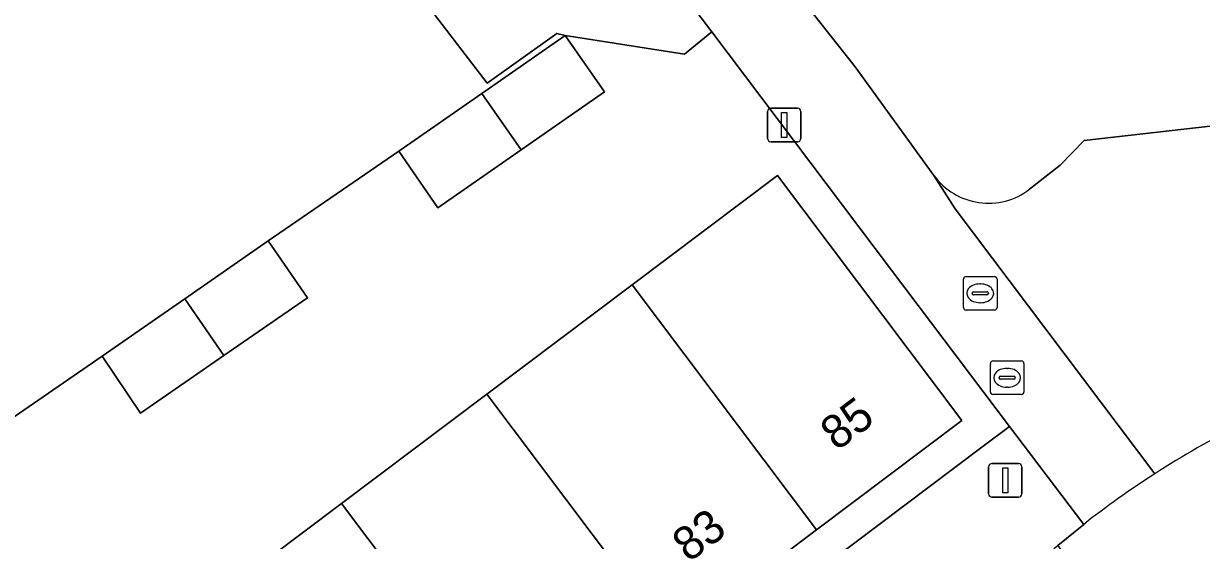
# Model space of a CAD drawing. Extents: x 160377 to 161131, y 383938 to 384853.
# Drawn here: x 160494.57 to 160529.76, y 384729.14 to 384744.58 of the extents above; entities that cross this region are included whole.
import ezdxf

# ---------------------------------------------------------------- set-up
doc = ezdxf.new("R2010")
doc.units = 0
for name, color, linetype in [('IMGEO_Brandkraan', 7, 'Continuous'), ('IMGEO_Erf', 7, 'Continuous'), ('IMGEO_Lichtmast', 7, 'Continuous'), ('IMGEO_Pand', 7, 'Continuous'), ('IMGEO_Pand_nummerreeks', 7, 'Continuous'), ('IMGEO_Rijbaan_lokaal_open', 7, 'Continuous'), ('IMGEO_Rioolput', 7, 'Continuous'), ('IMGEO_Voetpad_open', 7, 'Continuous')]:
    doc.layers.add(name, color=color, linetype=linetype)

msp = doc.modelspace()

# ---------------------------------------------------------------- linework, layer by layer
at = {"layer": 'IMGEO_Brandkraan'}
for p, q in [((160523.452, 384733.576), (160523.452, 384734.428)), ((160523.527, 384734.502), (160524.379, 384734.502)), ((160524.453, 384734.428), (160524.453, 384733.576)), ((160523.94, 384734.282), (160523.965, 384734.282)), ((160523.711, 384733.996), (160523.711, 384734.008)), ((160524.149, 384733.959), (160523.751, 384733.959)), ((160523.754, 384734.045), (160524.152, 384734.045)), ((160523.963, 384733.722), (160523.938, 384733.722)), ((160524.195, 384734.008), (160524.195, 384733.996)), ((160524.379, 384733.502), (160523.527, 384733.502))]:
    msp.add_line(p, q, dxfattribs=at)
for points in [[(160523.452, 384733.576), (160523.452, 384734.428)], [(160523.527, 384734.502), (160524.379, 384734.502)], [(160524.453, 384734.428), (160524.453, 384733.576)], [(160524.379, 384733.502), (160523.527, 384733.502)]]:
    msp.add_lwpolyline(points, dxfattribs=at)
for centre, radius, start, end in [((160523.529, 384734.426), 0.0765, 91.552, 178.448), ((160523.529, 384734.426), 0.0765, 91.552, 178.448), ((160524.377, 384734.426), 0.0765, 1.552, 88.448), ((160524.377, 384734.426), 0.0765, 1.552, 88.448), ((160523.751, 384734.005), 0.0403, 85.8775, 175.7526), ((160523.748, 384733.995), 0.0366, 178.938, 274.7102), ((160524.152, 384734.002), 0.043, 264.8664, 352.4533), ((160524.156, 384734.007), 0.0386, 1.7309, 96.639), ((160523.529, 384733.578), 0.0765, 181.552, 268.448), ((160523.529, 384733.578), 0.0765, 181.552, 268.448), ((160524.377, 384733.578), 0.0765, 271.552, 358.448), ((160524.377, 384733.578), 0.0765, 271.552, 358.448)]:
    msp.add_arc(centre, radius, start, end, dxfattribs=at)
for centre, major_axis, ratio, start_param, end_param in [((160523.939, 384734.002), (-0.387, 0.002), 0.722429, 4.712389, 7.853982), ((160523.964, 384734.002), (-0.39, 0.002), 0.717154, 1.570796, 4.712389)]:
    msp.add_ellipse(centre, major_axis=major_axis, ratio=ratio, start_param=start_param, end_param=end_param, dxfattribs=at)
at = {"layer": 'IMGEO_Erf'}
for points in [[(160524.622, 384739.63), (160525.541, 384740.344), (160526.258, 384741.081), (160536.933, 384742.304), (160543.963, 384743.13), (160555.551, 384744.527), (160559.981, 384745.061), (160564.978, 384745.652), (160564.727, 384747.719), (160559.736, 384747.162), (160557.652, 384764.913)], [(160512.869, 384751.723), (160515.948, 384747.677), (160519.414, 384743.287), (160521.768, 384740.04)], [(160501.88, 384738.087), (160505.784, 384740.768), (160508.262, 384742.49), (160510.755, 384744.223), (160510.5, 384744.276), (160508.419, 384742.793), (160504.852, 384747.466)], [(160487, 384704.676), (160523.198, 384731.929), (160524.022, 384732.549), (160520.501, 384737.216), (160515.137, 384744.326), (160514.313, 384743.664), (160510.755, 384744.223), (160511.925, 384742.54), (160509.436, 384740.806), (160506.946, 384739.072), (160505.784, 384740.768), (160501.88, 384738.087), (160503.052, 384736.392), (160500.558, 384734.669), (160498.065, 384732.947), (160496.919, 384734.648), (160492.969, 384731.932)], [(160491.047, 384720.451), (160495.388, 384723.716), (160499.729, 384726.981), (160504.07, 384730.246), (160508.411, 384733.512), (160512.752, 384736.777), (160517.093, 384740.042), (160522.597, 384732.728), (160518.257, 384729.462), (160513.917, 384726.196), (160509.576, 384722.929), (160505.236, 384719.663), (160500.896, 384716.397), (160496.556, 384713.131), (160492.216, 384709.865)], [(160466.304, 384713.501), (160479.098, 384722.358), (160481.586, 384724.08), (160484.067, 384725.798), (160488.006, 384728.518), (160490.479, 384730.219), (160492.969, 384731.932), (160496.919, 384734.648), (160499.39, 384736.361), (160501.88, 384738.087)]]:
    msp.add_lwpolyline(points, dxfattribs=at)
for centre, start, end in [((160523.393, 384741.223), 216.0468, 261.8373), ((160523.395, 384741.222), 261.7768, 307.6097)]:
    msp.add_arc(centre, 2.01, start, end, dxfattribs=at)
at = {"layer": 'IMGEO_Lichtmast'}
for p, q in [((160516.798, 384741.149), (160516.798, 384741.949)), ((160516.798, 384741.949), (160516.798, 384741.149)), ((160516.898, 384742.049), (160517.688, 384742.049)), ((160517.688, 384742.049), (160516.898, 384742.049)), ((160517.788, 384741.949), (160517.788, 384741.149)), ((160517.788, 384741.149), (160517.788, 384741.949)), ((160517.688, 384741.049), (160516.898, 384741.049)), ((160516.898, 384741.049), (160517.688, 384741.049)), ((160523.4, 384730.54), (160523.4, 384731.34)), ((160523.4, 384731.34), (160523.4, 384730.54)), ((160523.5, 384731.44), (160524.29, 384731.44)), ((160524.29, 384731.44), (160523.5, 384731.44)), ((160524.39, 384731.34), (160524.39, 384730.54)), ((160524.39, 384730.54), (160524.39, 384731.34)), ((160524.29, 384730.44), (160523.5, 384730.44)), ((160523.5, 384730.44), (160524.29, 384730.44))]:
    msp.add_line(p, q, dxfattribs=at)
for points in [[(160517.218, 384741.924), (160517.368, 384741.924), (160517.368, 384741.174), (160517.218, 384741.174), (160517.218, 384741.924)], [(160523.82, 384731.315), (160523.97, 384731.315), (160523.97, 384730.565), (160523.82, 384730.565), (160523.82, 384731.315)]]:
    msp.add_lwpolyline(points, dxfattribs=at)
for centre, start, end in [((160516.898, 384741.949), 90, 180), ((160516.898, 384741.949), 90, 180), ((160517.688, 384741.949), 0, 90), ((160517.688, 384741.949), 360, 90), ((160516.898, 384741.149), 180, 270), ((160516.898, 384741.149), 180, 270), ((160517.688, 384741.149), 270, 0), ((160517.688, 384741.149), 270, 0), ((160523.5, 384731.34), 90, 180), ((160523.5, 384731.34), 90, 180), ((160524.29, 384731.34), 0, 90), ((160524.29, 384731.34), 360, 90), ((160523.5, 384730.54), 180, 270), ((160523.5, 384730.54), 180, 270), ((160524.29, 384730.54), 270, 0), ((160524.29, 384730.54), 270, 0)]:
    msp.add_arc(centre, 0.1, start, end, dxfattribs=at)
at = {"layer": 'IMGEO_Pand'}
for points in [[(160510.755, 384744.223), (160508.262, 384742.49), (160509.436, 384740.806), (160511.925, 384742.54)], [(160508.262, 384742.49), (160505.784, 384740.768), (160506.946, 384739.072), (160509.436, 384740.806)], [(160517.093, 384740.042), (160512.752, 384736.777), (160518.257, 384729.462), (160522.597, 384732.728)], [(160501.88, 384738.087), (160499.39, 384736.361), (160500.558, 384734.669), (160503.052, 384736.392)], [(160512.752, 384736.777), (160508.411, 384733.512), (160513.917, 384726.196), (160518.257, 384729.462)], [(160500.558, 384734.669), (160499.39, 384736.361), (160496.919, 384734.648), (160498.065, 384732.947)], [(160508.411, 384733.512), (160504.07, 384730.246), (160509.576, 384722.929), (160513.917, 384726.196)], [(160504.07, 384730.246), (160499.729, 384726.981), (160505.236, 384719.663), (160509.576, 384722.929)]]:
    msp.add_lwpolyline(points, close=True, dxfattribs=at)
at = {"layer": 'IMGEO_Rijbaan_lokaal_open'}
for points in [[(160507.423, 384755.369), (160506.72, 384748.893), (160504.852, 384747.466), (160508.419, 384742.793), (160510.5, 384744.276), (160510.755, 384744.223), (160514.313, 384743.664), (160515.137, 384744.326), (160510.728, 384750.113)], [(160526.24, 384729.625), (160525.467, 384728.995), (160528.337, 384724.941), (160529.167, 384725.508)]]:
    msp.add_lwpolyline(points, dxfattribs=at)
for centre, radius, start, end in [((160543.659, 384707.369), 28.264, 116.7526, 122.7707), ((160543.446, 384707.712), 27.861, 122.7836, 128.1382)]:
    msp.add_arc(centre, radius, start, end, dxfattribs=at)
at = {"layer": 'IMGEO_Rioolput'}
for p, q in [((160522.65, 384736.097), (160522.65, 384736.949)), ((160522.725, 384737.023), (160523.577, 384737.023)), ((160523.651, 384736.949), (160523.651, 384736.097)), ((160522.909, 384736.517), (160522.909, 384736.529)), ((160522.952, 384736.566), (160523.35, 384736.566)), ((160523.138, 384736.803), (160523.163, 384736.803)), ((160523.393, 384736.529), (160523.393, 384736.517)), ((160523.347, 384736.48), (160522.949, 384736.48)), ((160523.161, 384736.243), (160523.136, 384736.243)), ((160523.577, 384736.023), (160522.725, 384736.023))]:
    msp.add_line(p, q, dxfattribs=at)
for points in [[(160522.65, 384736.097), (160522.65, 384736.949)], [(160522.725, 384737.023), (160523.577, 384737.023)], [(160523.651, 384736.949), (160523.651, 384736.097)], [(160523.577, 384736.023), (160522.725, 384736.023)]]:
    msp.add_lwpolyline(points, dxfattribs=at)
for centre, radius, start, end in [((160522.727, 384736.947), 0.0765, 91.552, 178.448), ((160522.727, 384736.947), 0.0765, 91.552, 178.448), ((160523.575, 384736.947), 0.0765, 1.552, 88.448), ((160523.575, 384736.947), 0.0765, 1.552, 88.448), ((160522.949, 384736.526), 0.0403, 85.8775, 175.7526), ((160523.354, 384736.528), 0.0386, 1.7309, 96.639), ((160522.946, 384736.516), 0.0366, 178.938, 274.7102), ((160523.35, 384736.523), 0.043, 264.8664, 352.4533), ((160522.727, 384736.099), 0.0765, 181.552, 268.448), ((160522.727, 384736.099), 0.0765, 181.552, 268.448), ((160523.575, 384736.099), 0.0765, 271.552, 358.448), ((160523.575, 384736.099), 0.0765, 271.552, 358.448)]:
    msp.add_arc(centre, radius, start, end, dxfattribs=at)
for centre, major_axis, ratio, start_param, end_param in [((160523.137, 384736.523), (-0.387, 0.002), 0.722429, 4.712389, 7.853982), ((160523.162, 384736.523), (-0.39, 0.002), 0.717154, 1.570796, 4.712389)]:
    msp.add_ellipse(centre, major_axis=major_axis, ratio=ratio, start_param=start_param, end_param=end_param, dxfattribs=at)
at = {"layer": 'IMGEO_Voetpad_open'}
for points in [[(160621.236, 384751.923), (160621.017, 384753.86), (160615.335, 384751.518), (160610.326, 384750.936), (160564.978, 384745.652), (160559.981, 384745.061), (160555.551, 384744.527), (160543.963, 384743.13), (160536.933, 384742.304), (160526.258, 384741.081), (160525.541, 384740.344), (160524.622, 384739.63)], [(160519.414, 384743.287), (160515.948, 384747.677), (160512.869, 384751.723), (160510.728, 384750.113), (160515.137, 384744.326), (160520.501, 384737.216), (160524.022, 384732.549), (160526.24, 384729.625)], [(160528.36, 384731.135), (160522.398, 384739.045), (160521.768, 384740.04), (160519.414, 384743.287)], [(160521.768, 384740.04), (160522.398, 384739.045), (160528.36, 384731.135)], [(160525.346, 384728.904), (160525.467, 384728.995), (160526.24, 384729.625), (160524.022, 384732.549), (160523.198, 384731.929), (160487, 384704.676), (160487.022, 384676.465), (160524.356, 384632.684), (160526.662, 384629.966)]]:
    msp.add_lwpolyline(points, dxfattribs=at)
for centre, radius, start, end in [((160523.393, 384741.223), 2.01, 216.0468, 261.8373), ((160523.395, 384741.222), 2.01, 261.7768, 307.6097), ((160543.659, 384707.369), 28.264, 116.7526, 122.7707), ((160543.446, 384707.712), 27.861, 122.7836, 128.1382)]:
    msp.add_arc(centre, radius, start, end, dxfattribs=at)

# ---------------------------------------------------------------- texts
at = {"layer": 'IMGEO_Pand_nummerreeks'}
for s, p in [('85', (160518.866, 384731.797)), ('83', (160514.443, 384728.468))]:
    msp.add_text(s, height=1, rotation=36.9615, dxfattribs=at).set_placement(p)

doc.saveas('drawing.dxf')
